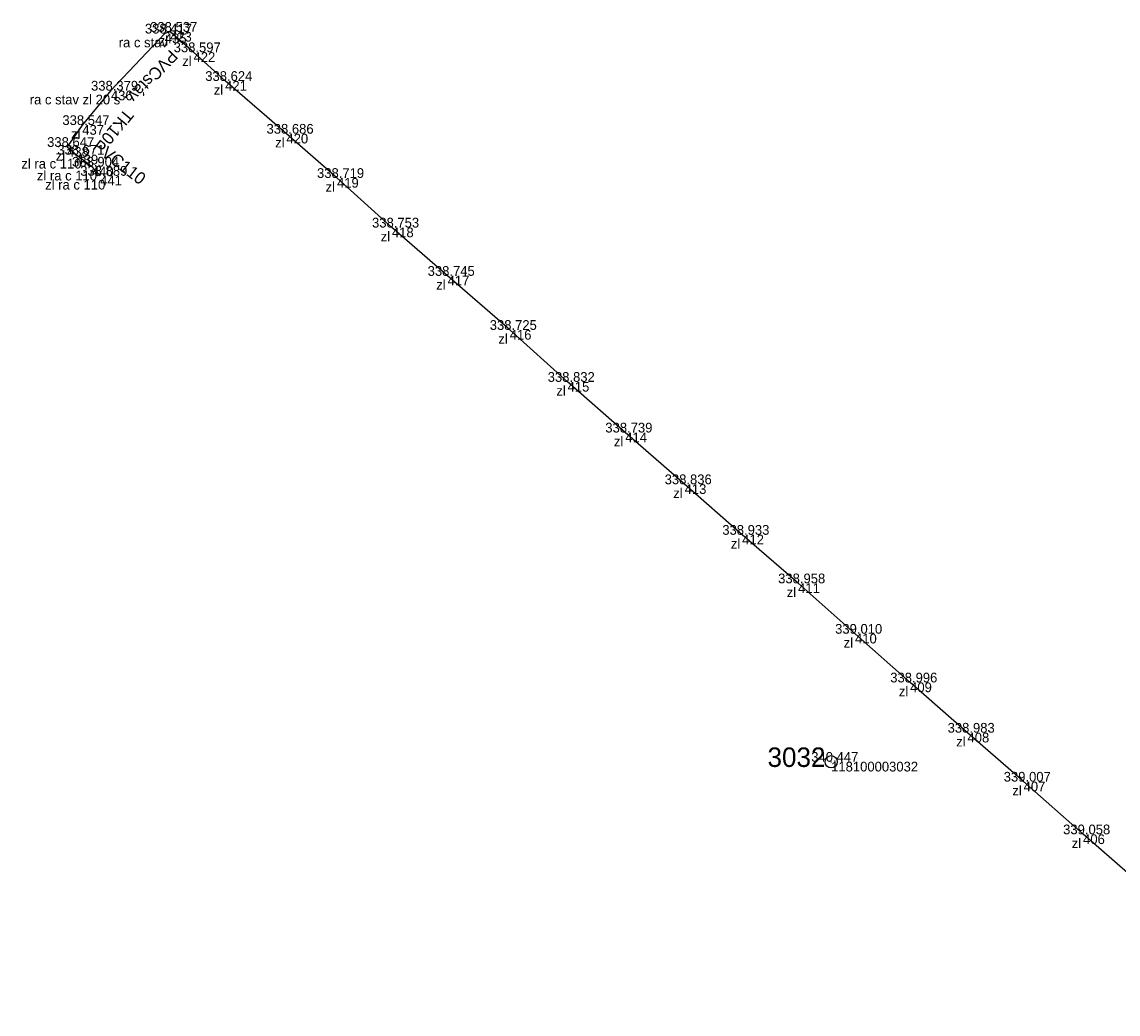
# Model space of a CAD drawing. Extents: x -727171 to -722443, y -945718 to -941834.
# Drawn here: x -726097.1 to -725962.1, y -942232.8 to -942110.6 of the extents above; entities that cross this region are included whole.
import ezdxf

# ---------------------------------------------------------------- set-up
doc = ezdxf.new("R2010")
doc.units = 0
for name, color, linetype in [('Vrstva 28', 7, 'Continuous'), ('Vrstva 35', 7, 'Continuous'), ('Vrstva 60', 7, 'Continuous'), ('Vrstva 61', 7, 'Continuous'), ('Vrstva 62', 7, 'Continuous'), ('Vrstva 63', 7, 'Continuous')]:
    doc.layers.add(name, color=color, linetype=linetype)

msp = doc.modelspace()

# ---------------------------------------------------------------- linework, layer by layer
at = {"layer": 'Vrstva 28'}
for points in [[(-726079.52, -942112.04), (-726086.16, -942119.07)], [(-725941.44, -942232.83), (-725942.64, -942231.48), (-725950.18, -942224.79), (-725958.66, -942217.39), (-725966.39, -942210.69), (-725973.72, -942204.2), (-725980.63, -942198.17), (-725987.7, -942191.98), (-725994.49, -942185.98), (-726001.5, -942179.77), (-726008.39, -942173.79), (-726015.48, -942167.56), (-726022.79, -942161.19), (-726029.9, -942154.95), (-726037.03, -942148.55), (-726044.68, -942141.89), (-726051.54, -942135.94), (-726058.31, -942129.83), (-726064.54, -942124.38), (-726072.09, -942117.88), (-726075.98, -942114.34), (-726078.88, -942111.83), (-726079.52, -942112.04)], [(-726086.16, -942119.07), (-726089.69, -942123.31), (-726091.56, -942126.01), (-726090.41, -942126.97), (-726088.5, -942128.44), (-726087.48, -942129.56)], [(-726090.41, -942126.97), (-726088.5, -942128.44), (-726087.48, -942129.56)]]:
    msp.add_lwpolyline(points, dxfattribs=at)
at = {"layer": 'Vrstva 35'}
for points in [[(-726079.52, -942112.04), (-726086.16, -942119.07)], [(-726090.41, -942126.97), (-726088.5, -942128.44), (-726087.48, -942129.56)]]:
    msp.add_lwpolyline(points, dxfattribs=at)
at = {"layer": 'Vrstva 60'}
for p, q in [((-726079.52, -942112.04), (-726079.52, -942112.04)), ((-726078.88, -942111.83), (-726078.88, -942111.83)), ((-726075.98, -942114.34), (-726075.98, -942114.34)), ((-726086.16, -942119.07), (-726086.16, -942119.07)), ((-726072.09, -942117.88), (-726072.09, -942117.88)), ((-726089.69, -942123.31), (-726089.69, -942123.31)), ((-726064.54, -942124.38), (-726064.54, -942124.38)), ((-726091.56, -942126.01), (-726091.56, -942126.01)), ((-726090.41, -942126.97), (-726090.41, -942126.97)), ((-726088.5, -942128.44), (-726088.5, -942128.44)), ((-726087.48, -942129.56), (-726087.48, -942129.56)), ((-726058.31, -942129.83), (-726058.31, -942129.83)), ((-726051.54, -942135.94), (-726051.54, -942135.94)), ((-726044.68, -942141.89), (-726044.68, -942141.89)), ((-726037.03, -942148.55), (-726037.03, -942148.55)), ((-726029.9, -942154.95), (-726029.9, -942154.95)), ((-726022.79, -942161.19), (-726022.79, -942161.19)), ((-726015.48, -942167.56), (-726015.48, -942167.56)), ((-726008.39, -942173.79), (-726008.39, -942173.79)), ((-726001.5, -942179.77), (-726001.5, -942179.77)), ((-725994.49, -942185.98), (-725994.49, -942185.98)), ((-725987.7, -942191.98), (-725987.7, -942191.98)), ((-725980.63, -942198.17), (-725980.63, -942198.17)), ((-725997.43, -942201.75), (-725997.43, -942201.75)), ((-725973.72, -942204.2), (-725973.72, -942204.2)), ((-725966.39, -942210.69), (-725966.39, -942210.69))]:
    msp.add_line(p, q, dxfattribs=at)
at = {"layer": 'Vrstva 63'}
msp.add_line((-725997.48, -942201.75), (-725997.38, -942201.75), dxfattribs=at)
msp.add_circle((-725997.43, -942201.75), 0.756, dxfattribs=at)

# ---------------------------------------------------------------- texts
at = {"layer": 'Vrstva 28'}
msp.add_text('TK10', height=1.5, rotation=230.1705, dxfattribs=at).set_placement((-726084.4, -942121.21))
at = {"layer": 'Vrstva 35'}
for s, rotation, p in [('PVCstáv.', 226.6722, (-726078.88, -942113.93)), ('PVC110', 322.5081, (-726088.53, -942126.21))]:
    msp.add_text(s, height=1.5, rotation=rotation, dxfattribs=at).set_placement(p)
at = {"layer": 'Vrstva 60'}
for s, p in [('435', (-726079.52, -942113.24)), ('423', (-726078.88, -942113.03)), ('422', (-726075.98, -942115.54)), ('436', (-726086.16, -942120.27)), ('421', (-726072.09, -942119.08)), ('437', (-726089.69, -942124.51)), ('420', (-726064.54, -942125.58)), ('438', (-726091.56, -942127.21)), ('439', (-726090.41, -942128.17)), ('440', (-726088.5, -942129.64)), ('441', (-726087.48, -942130.76)), ('419', (-726058.31, -942131.03)), ('418', (-726051.54, -942137.14)), ('417', (-726044.68, -942143.08)), ('416', (-726037.03, -942149.75)), ('415', (-726029.9, -942156.15)), ('414', (-726022.79, -942162.39)), ('413', (-726015.48, -942168.76)), ('412', (-726008.39, -942174.98)), ('411', (-726001.5, -942180.97)), ('410', (-725994.49, -942187.18)), ('409', (-725987.7, -942193.18)), ('408', (-725980.63, -942199.37)), ('118100003032', (-725997.43, -942202.95)), ('407', (-725973.72, -942205.4)), ('406', (-725966.39, -942211.89))]:
    msp.add_text(s, height=1.2, dxfattribs=at).set_placement(p)
at = {"layer": 'Vrstva 61'}
for s, p in [('338.417', (-726081.97, -942112.04)), ('338.537', (-726081.33, -942111.83)), ('338.597', (-726078.43, -942114.34)), ('338.624', (-726074.54, -942117.88)), ('338.379', (-726088.61, -942119.07)), ('338.547', (-726092.14, -942123.31)), ('338.686', (-726066.99, -942124.38)), ('338.647', (-726094.02, -942126.01)), ('338.671', (-726092.77, -942126.97)), ('338.904', (-726090.95, -942128.44)), ('338.889', (-726089.94, -942129.56)), ('338.719', (-726060.77, -942129.83)), ('338.753', (-726053.99, -942135.94)), ('338.745', (-726047.14, -942141.89)), ('338.725', (-726039.49, -942148.55)), ('338.832', (-726032.35, -942154.95)), ('338.739', (-726025.25, -942161.19)), ('338.836', (-726017.94, -942167.56)), ('338.933', (-726010.84, -942173.79)), ('338.958', (-726003.96, -942179.77)), ('339.010', (-725996.94, -942185.98)), ('338.996', (-725990.15, -942191.98)), ('338.983', (-725983.08, -942198.17)), ('340.447', (-725999.88, -942201.75)), ('339.007', (-725976.17, -942204.2)), ('339.058', (-725968.85, -942210.69))]:
    msp.add_text(s, height=1.2, dxfattribs=at).set_placement(p)
at = {"layer": 'Vrstva 62'}
for s, p in [('zl', (-726080.28, -942113.53)), ('ra c stav', (-726085.2, -942113.74)), ('zl', (-726077.37, -942116.04)), ('zl', (-726073.49, -942119.58)), ('ra c stav zl 20 s', (-726096.16, -942120.77)), ('zl', (-726091.08, -942125.01)), ('zl', (-726065.93, -942126.08)), ('zl', (-726092.96, -942127.71)), ('zl ra c 110', (-726097.19, -942128.67)), ('zl ra c 110', (-726095.28, -942130.14)), ('zl ra c 110', (-726094.26, -942131.26)), ('zl', (-726059.71, -942131.53)), ('zl', (-726052.93, -942137.64)), ('zl', (-726046.08, -942143.58)), ('zl', (-726038.43, -942150.25)), ('zl', (-726031.29, -942156.65)), ('zl', (-726024.19, -942162.89)), ('zl', (-726016.88, -942169.26)), ('zl', (-726009.79, -942175.48)), ('zl', (-726002.9, -942181.47)), ('zl', (-725995.89, -942187.68)), ('zl', (-725989.09, -942193.68)), ('zl', (-725982.02, -942199.87)), ('zl', (-725975.11, -942205.9)), ('zl', (-725967.79, -942212.39))]:
    msp.add_text(s, height=1.2, dxfattribs=at).set_placement(p)
at = {"layer": 'Vrstva 63'}
msp.add_text('3032', height=2.4, dxfattribs=at).set_placement((-726005.27, -942202.39))

doc.saveas('drawing.dxf')
